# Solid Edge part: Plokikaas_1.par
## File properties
Author: KULL
Template: Iso Metric Part.par
Last saved by: KULL
Revision: 9
Application: Solid Edge
Accuracy: 0,990
Face Style: Model Default
Fill Style: Normal
Coef. of Thermal Exp: 0.0
Thermal Conductivity: 0.0
Specific Heat: 0.0
Modulus of Elasticity: 0.0
Poisson's Ratio: 0.0
Yield Stress: 0.0
Ultimate Stress: 0.0
Elongation: 0.0
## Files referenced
..\..\Mootor_ASM_1.asm
hiplokk 2.par
lG:\Haapsalu Kolledz\Solid edge leong\Solid edge Sync practice\ROVER_Heiko_Kull_EKSAM\Mootor\Mootor_ASM_1.asm
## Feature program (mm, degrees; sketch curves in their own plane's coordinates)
pattern "unnamed Pattern 1"
pattern "unnamed Pattern 2"
Other named dimensions: "Pattern_1": XDirCount = 5; XDirSpacing = 18 mm | "Pattern_2": XDirCount = 5; XDirSpacing = 18 mm
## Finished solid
Body 1: solid body, 128 faces, 235 edges, 104 vertices.
  Faces by surface: spline 40, plane 27, cylinder 26, torus 25, cone 10
  Edges by curve: circle 71, line 60, intersection 54, spline 30, ellipse 20
Body 2: sheet body, 1 face, 13 edges, 8 vertices.
  Faces by surface: plane 1
  Edges by curve: circle 9, line 4
Bounding box of the edges (mm; curved faces can reach further): 96.000 x 29.454 x 27.888, from (-48, 15.1609, 37.8813) to (48, 44.6145, 65.7694).
Cylindrical faces by radius (mm): R0.7583 x10, R3 x4, R5 x8, R8 x4
Conical faces (half-angle, radius in mm at the cone's reference point): 0.9869 deg R2.4867 x10
Toroidal faces (ring radius, tube radius in mm): R2.1444 r0.4 x10, R2.582 r1.8241 x10, R3.3542 r4 x5
Planar faces by outward normal: +x 1, -x 1, oblique 25
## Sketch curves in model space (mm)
line (36, 34.3873, 57.1877) -> (-36, 34.3873, 57.1877)
line (36, 28.3292, 45.3007) -> (36, 41.2745, 52.7747)
line (36, 26.031, 47.2291) -> (36, 30.6273, 43.3724)
line (36, 26.031, 47.2291) -> (36, 37.0524, 60.3638)
line (36, 40.115, 43.2436) -> (-36, 40.115, 43.2436)
circle centre (-36, 40.115, 43.2436) radius 2
circle centre (-18, 40.115, 43.2436) radius 2
circle centre (0, 40.115, 43.2436) radius 2
circle centre (18, 40.115, 43.2436) radius 2
line (-42, 40.0885, 35.4334) -> (-30, 40.0885, 35.4334)
line (-24, 40.0885, 35.4334) -> (-12, 40.0885, 35.4334)
line (-6, 40.0885, 35.4334) -> (6, 40.0885, 35.4334)
line (12, 40.0885, 35.4334) -> (24, 40.0885, 35.4334)
line (30, 40.0885, 35.4334) -> (42, 40.0885, 35.4334)
line (48, 43.9453, 40.0297) -> (-48, 43.9453, 40.0297)
circle centre (-36, 43.9453, 40.0297) radius 2
circle centre (-18, 43.9453, 40.0297) radius 2
circle centre (0, 43.9453, 40.0297) radius 2
circle centre (18, 43.9453, 40.0297) radius 2
circle centre (36, 43.9453, 40.0297) radius 2
line (48, 21.2893, 49.9025) -> (48, 29.4872, 43.0236)
arc centre (40, 29.4872, 43.0236) radius 8 from (48, 29.4872, 43.0236) through (45.4899, 33.9448, 39.2833) to (40, 35.6155, 37.8813)
line (40, 35.6155, 37.8813) -> (-40, 35.6155, 37.8813)
arc centre (-40, 29.4872, 43.0236) radius 8 from (-40, 35.6155, 37.8813) through (-45.819, 33.6927, 39.4948) to (-48, 29.4872, 43.0236)
line (-48, 29.4872, 43.0236) -> (-48, 21.2893, 49.9025)
arc centre (-40, 21.2893, 49.9025) radius 8 from (-48, 21.2893, 49.9025) through (-45.4899, 16.8317, 53.6428) to (-40, 15.1609, 55.0448)
line (-40, 15.1609, 55.0448) -> (40, 15.1609, 55.0448)
arc centre (40, 21.2893, 49.9025) radius 8 from (40, 15.1609, 55.0448) through (45.819, 17.0838, 53.4313) to (48, 21.2893, 49.9025)
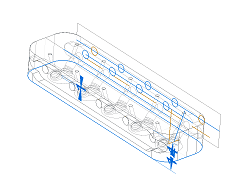
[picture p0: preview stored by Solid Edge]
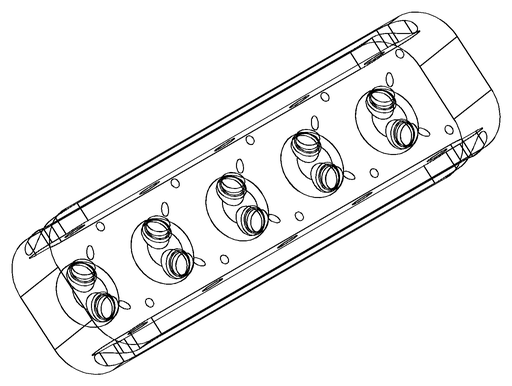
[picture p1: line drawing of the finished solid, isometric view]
